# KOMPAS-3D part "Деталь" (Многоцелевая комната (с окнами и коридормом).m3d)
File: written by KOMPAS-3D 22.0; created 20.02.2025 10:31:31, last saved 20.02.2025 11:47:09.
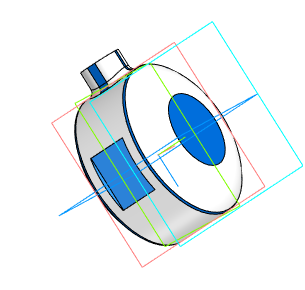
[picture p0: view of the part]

Document properties: Автор: Пользователь Windows; Полное имя файла: C:\Users\Student\Documents\Картошечка\База Сабнатика\Многоцелевая комната\Многоцелевая комната (с окнами и коридормом).m3d

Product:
- Part/product: Деталь
    Масса: 0.422739

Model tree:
1. Эскиз:3
2. Элемент вращения:1
     Угол 1 = 360
3. Скругление:1  (with: Элемент вращения:1)
     Радиус = 1
4. Смещенная плоскость:1
     Расстояние = 25
5. Эскиз:4
6. Элемент выдавливания:1
     Расстояние 2 = 2
7. Зеркальный массив:1
8. Экземпляр ( 1 )
9. Экземпляр ( 2 )  (with: Элемент выдавливания:1)
10. Эскиз:5
11. Элемент выдавливания:2
     Расстояние 1 = 32.5
12. Скругление:2  (with: Элемент выдавливания:2)
     Радиус = 2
